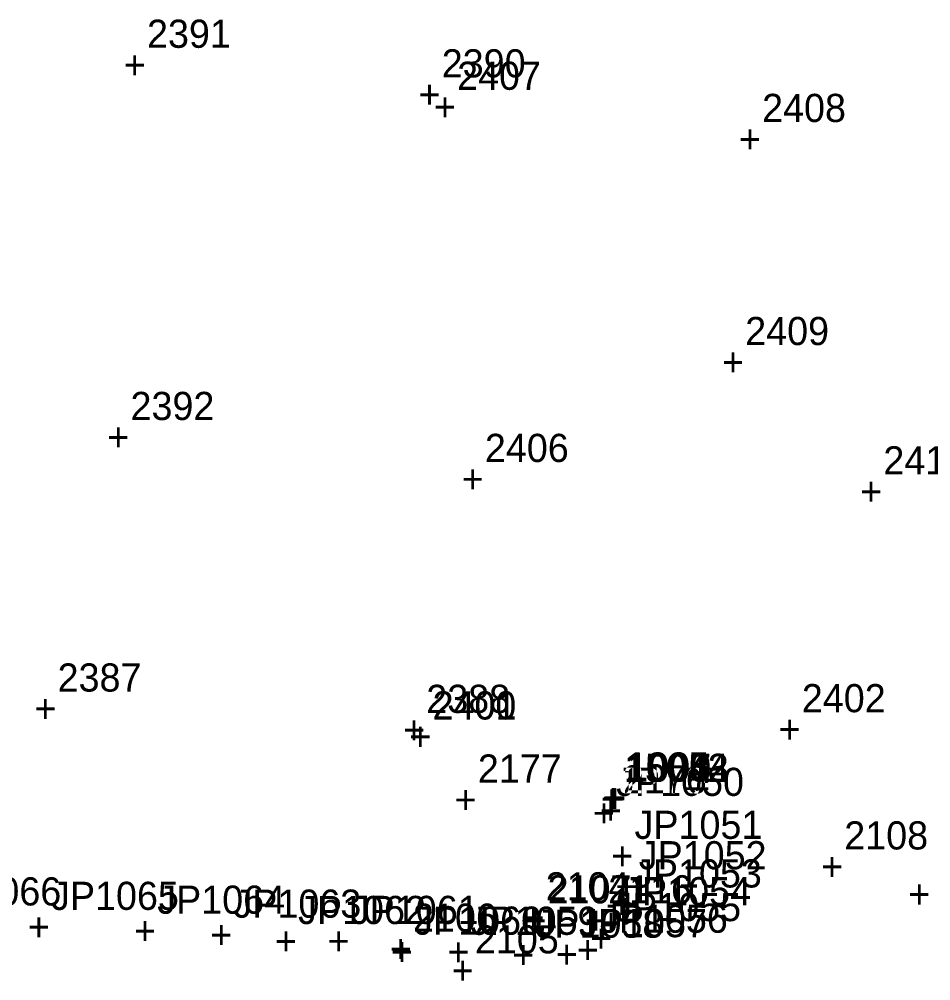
# Model space of a CAD drawing. Extents: x 2192192 to 2193475, y 863716 to 864270.
# Drawn here: x 2192506.3 to 2192587.2, y 863944.6 to 864029.9 of the extents above; entities that cross this region are included whole.
import ezdxf

# ---------------------------------------------------------------- set-up
doc = ezdxf.new("R2010")
doc.units = 0
for name, color, linetype in [('S_Control_Geodetic_ControlPoint', 7, 'Continuous'), ('S_Control_Survey_Traverse_Chek', 7, 'Continuous'), ('S_Control_Temp_Traverse', 7, 'Continuous'), ('S_Drainage_Ditch_Line', 7, 'Continuous'), ('S_Ground_Elevation', 7, 'Continuous'), ('S_Ground_LevelString', 7, 'Continuous'), ('S_Roadway_Edge_Pavement', 7, 'Continuous'), ('S_Roadway_Edge_Shoulder', 7, 'Continuous'), ('S_Roadway_Edge_TW', 7, 'Continuous'), ('S_Trees_TreeLine', 7, 'Continuous'), ('S_Utilities_GuyWire3', 7, 'Continuous'), ('S_Utilities_Pole_Power', 7, 'Continuous'), ('S_Utilities_UG_Telephone', 7, 'Continuous')]:
    doc.layers.add(name, color=color, linetype=linetype)

msp = doc.modelspace()

# ---------------------------------------------------------------- texts
at = {"layer": 'S_Control_Geodetic_ControlPoint'}
msp.add_text('+', height=2.5, dxfattribs=at).set_placement((2192585.184, 863951.043))
msp.add_text('+', height=2.5, dxfattribs=at).set_placement((2192585.184, 863951.043))
msp.add_text('+', height=2.5, dxfattribs=at).set_placement((2192585.184, 863951.043))
msp.add_text('+', height=2.5, dxfattribs=at).set_placement((2192585.184, 863951.043))
msp.add_text('+', height=2.5, dxfattribs=at).set_placement((2192585.184, 863951.043))
msp.add_text('+', height=2.5, dxfattribs=at).set_placement((2192585.184, 863951.043))
msp.add_text('+', height=2.5, dxfattribs=at).set_placement((2192585.184, 863951.043))
msp.add_text('+', height=2.5, dxfattribs=at).set_placement((2192585.184, 863951.043))
msp.add_text('+', height=2.5, dxfattribs=at).set_placement((2192585.184, 863951.043))
at = {"layer": 'S_Control_Survey_Traverse_Chek'}
for s, height, p in [('1004', 2.4999, (2192560.057, 863962.261)), ('1005', 2.4999, (2192560.079, 863962.358)), ('1006', 2.4999, (2192560.116, 863962.258)), ('1001', 2.4999, (2192560.192, 863962.364)), ('1003', 2.4999, (2192560.253, 863962.336)), ('1000', 2.4999, (2192560.257, 863962.333)), ('1007', 2.4999, (2192560.26, 863962.267)), ('+', 2.5, (2192557.996, 863959.511)), ('+', 2.5, (2192558.018, 863959.608)), ('+', 2.5, (2192558.055, 863959.508)), ('+', 2.5, (2192558.131, 863959.614)), ('+', 2.5, (2192558.192, 863959.586)), ('+', 2.5, (2192558.196, 863959.583)), ('+', 2.5, (2192558.199, 863959.517))]:
    msp.add_text(s, height=height, dxfattribs=at).set_placement(p)
at = {"layer": 'S_Control_Temp_Traverse'}
for s, height, p in [('150', 2.4999, (2192559.957, 863962.249)), ('150_3', 2.4999, (2192559.957, 863962.249)), ('150_2', 2.4999, (2192559.957, 863962.249)), ('150_4', 2.4999, (2192559.957, 863962.249)), ('+', 2.5, (2192557.896, 863959.499)), ('+', 2.5, (2192557.896, 863959.499)), ('+', 2.5, (2192557.896, 863959.499)), ('+', 2.5, (2192557.896, 863959.499))]:
    msp.add_text(s, height=height, dxfattribs=at).set_placement(p)
at = {"layer": 'S_Drainage_Ditch_Line'}
for s, height, p in [('2410', 2.4999, (2192582.972, 863989.541)), ('+', 2.5, (2192580.911, 863986.791))]:
    msp.add_text(s, height=height, dxfattribs=at).set_placement(p)
at = {"layer": 'S_Ground_Elevation'}
for s, height, p in [('2391', 2.4999, (2192517.653, 864027.41)), ('+', 2.5, (2192515.592, 864024.66)), ('2390', 2.4999, (2192543.798, 864024.781)), ('2407', 2.4999, (2192545.159, 864023.68)), ('+', 2.5, (2192541.736, 864022.031)), ('2408', 2.4999, (2192572.215, 864020.824)), ('+', 2.5, (2192543.098, 864020.93)), ('+', 2.5, (2192570.154, 864018.074)), ('2409', 2.4999, (2192570.718, 864001.021)), ('+', 2.5, (2192568.657, 863998.271)), ('2392', 2.4999, (2192516.191, 863994.368)), ('+', 2.5, (2192514.13, 863991.618)), ('2406', 2.4999, (2192547.626, 863990.645)), ('+', 2.5, (2192545.565, 863987.895)), ('2387', 2.4999, (2192509.722, 863970.264)), ('2388', 2.4999, (2192542.424, 863968.37)), ('2400', 2.4999, (2192542.974, 863967.789)), ('2402', 2.4999, (2192575.74, 863968.43)), ('+', 2.5, (2192507.661, 863967.514)), ('+', 2.5, (2192573.679, 863965.68)), ('+', 2.5, (2192540.363, 863965.62)), ('+', 2.5, (2192540.913, 863965.039))]:
    msp.add_text(s, height=height, dxfattribs=at).set_placement(p)
at = {"layer": 'S_Ground_LevelString'}
for s, height, p in [('2116', 2.4999, (2192558.556, 863951.462)), ('+', 2.5, (2192556.495, 863948.712))]:
    msp.add_text(s, height=height, dxfattribs=at).set_placement(p)
at = {"layer": 'S_Roadway_Edge_Pavement'}
for s, height, p in [('2108', 2.4999, (2192579.503, 863956.247)), ('+', 2.5, (2192577.442, 863953.497)), ('2107', 2.4999, (2192553.19, 863951.464)), ('2106', 2.4999, (2192541.25, 863948.948)), ('+', 2.5, (2192551.129, 863948.714)), ('+', 2.5, (2192539.189, 863946.198))]:
    msp.add_text(s, height=height, dxfattribs=at).set_placement(p)
at = {"layer": 'S_Roadway_Edge_Shoulder'}
for s, height, p in [('2104', 2.4999, (2192553.017, 863951.727)), ('+', 2.5, (2192550.956, 863948.977))]:
    msp.add_text(s, height=height, dxfattribs=at).set_placement(p)
at = {"layer": 'S_Roadway_Edge_TW'}
for s, height, p in [('2105', 2.4999, (2192546.74, 863947.024)), ('+', 2.5, (2192544.678, 863944.274))]:
    msp.add_text(s, height=height, dxfattribs=at).set_placement(p)
at = {"layer": 'S_Trees_TreeLine'}
for s, height, p in [('2401', 2.4999, (2192542.993, 863967.783)), ('+', 2.5, (2192540.932, 863965.033))]:
    msp.add_text(s, height=height, dxfattribs=at).set_placement(p)
at = {"layer": 'S_Utilities_GuyWire3'}
for s, height, p in [('2177', 2.4999, (2192547.002, 863962.185)), ('+', 2.5, (2192544.941, 863959.435))]:
    msp.add_text(s, height=height, dxfattribs=at).set_placement(p)
at = {"layer": 'S_Utilities_Pole_Power'}
for s, height, p in [('2176', 2.4999, (2192559.87, 863961.227)), ('+', 2.5, (2192557.809, 863958.477))]:
    msp.add_text(s, height=height, dxfattribs=at).set_placement(p)
at = {"layer": 'S_Utilities_UG_Telephone'}
for s, height, p in [('JP1050', 2.4999, (2192559.268, 863961.001)), ('+', 2.5, (2192557.207, 863958.251)), ('JP1051', 2.4999, (2192560.899, 863957.189)), ('JP1052', 2.4999, (2192561.273, 863954.487)), ('+', 2.5, (2192558.838, 863954.439)), ('JP1053', 2.4999, (2192560.853, 863952.872)), ('JP1066', 2.4999, (2192498.707, 863951.278)), ('JP1065', 2.4999, (2192509.141, 863950.884)), ('+', 2.5, (2192559.212, 863951.737)), ('JP1054', 2.4999, (2192559.889, 863951.294)), ('JP1064', 2.4999, (2192518.56, 863950.544)), ('JP1063', 2.4999, (2192525.321, 863950.19)), ('JP1055', 2.4999, (2192559.011, 863949.885)), ('JP1062', 2.4999, (2192531.055, 863949.629)), ('JP1061', 2.4999, (2192535.733, 863949.635)), ('+', 2.5, (2192558.792, 863950.122)), ('JP1060', 2.4999, (2192541.349, 863948.682)), ('JP1059', 2.4999, (2192546.367, 863948.669)), ('JP1058', 2.4999, (2192552.116, 863948.411)), ('JP1057', 2.4999, (2192555.976, 863948.462)), ('JP1056', 2.4999, (2192557.831, 863948.854)), ('+', 2.5, (2192507.08, 863948.134)), ('+', 2.5, (2192516.499, 863947.794)), ('+', 2.5, (2192557.828, 863948.544)), ('+', 2.5, (2192523.26, 863947.441)), ('+', 2.5, (2192528.994, 863946.88)), ('+', 2.5, (2192533.672, 863946.885)), ('+', 2.5, (2192556.95, 863947.136)), ('+', 2.5, (2192555.77, 863946.104)), ('+', 2.5, (2192539.288, 863945.932)), ('+', 2.5, (2192544.306, 863945.919)), ('+', 2.5, (2192550.055, 863945.662)), ('+', 2.5, (2192553.915, 863945.712))]:
    msp.add_text(s, height=height, dxfattribs=at).set_placement(p)

doc.saveas('drawing.dxf')
